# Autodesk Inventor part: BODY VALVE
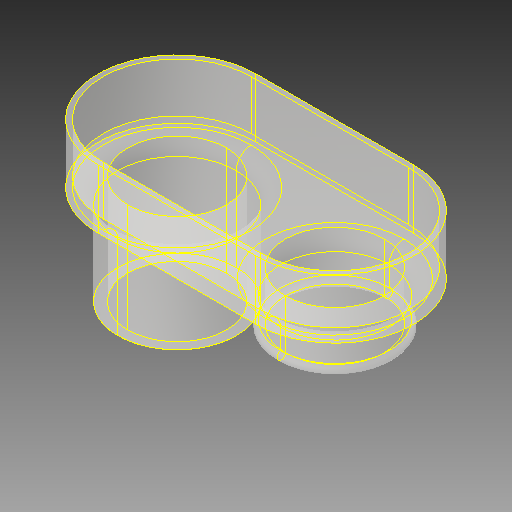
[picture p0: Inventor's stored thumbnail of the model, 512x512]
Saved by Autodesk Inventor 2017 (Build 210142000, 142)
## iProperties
Created: 2020-03
Part Number: BODY VALVE
Material: Generic
Document SubType Name: Modeling
Designer: user
Density: 1 g/cm^3
Appearance: Default
Author: user
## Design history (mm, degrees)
feature "Composite1"
body "Srf1"
